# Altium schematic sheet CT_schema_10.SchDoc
size 274 x 160 mm
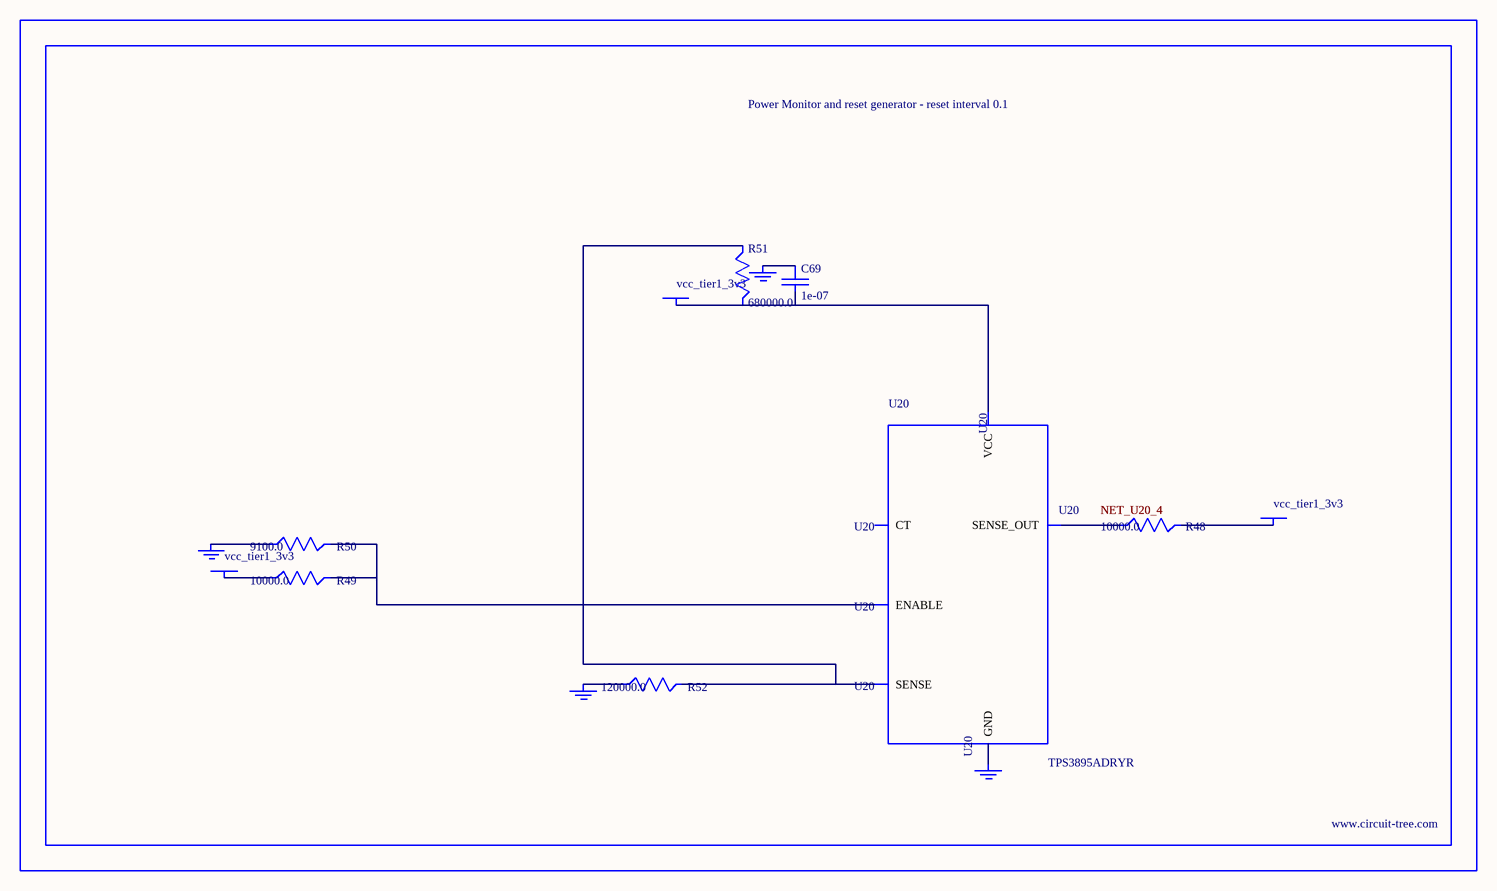
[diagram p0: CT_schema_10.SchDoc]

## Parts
BORDER9  (no value)
C69  1e-07  [C0402]
GND_INSTANCE_9_0  (no value)
GND_INSTANCE_9_1  (no value)
GND_INSTANCE_9_2  (no value)
GND_INSTANCE_9_3  (no value)
POWER_INSTANCE_9_0  vcc_tier1_3v3
POWER_INSTANCE_9_1  vcc_tier1_3v3
POWER_INSTANCE_9_2  vcc_tier1_3v3
R48  10000.0  [R0603]
R49  10000.0  [R0603]
R50  9100.0  [R0603]
R51  680000.0  [R0603]
R52  120000.0  [R0603]
U20  TPS3895ADRYR  [SON-6]

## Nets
NetC69_1: C69.1 GND_INSTANCE_9_2.0(GND)
NetC69_2: C69.2 POWER_INSTANCE_9_2.0(PWR) R51.2 U20.6(VCC)
NetGND_INSTANCE_9_0_0: GND_INSTANCE_9_0.0(GND) R50.1
NetGND_INSTANCE_9_1_0: GND_INSTANCE_9_1.0(GND) R52.1
NetGND_INSTANCE_9_3_0: GND_INSTANCE_9_3.0(GND) U20.2(GND)
NetPOWER_INSTANCE_9_0_0: POWER_INSTANCE_9_0.0(PWR) R49.1
NetPOWER_INSTANCE_9_1_0: POWER_INSTANCE_9_1.0(PWR) R48.2
NetR48_1: R48.1 U20.4(SENSE_OUT)
NetR49_2: R49.2 R50.2 U20.1(ENABLE)
NetR51_1: R51.1 R52.2 U20.3(SENSE)

Not connected (* = marked no-connect by the designer): U20 5(CT)

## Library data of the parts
BORDER9 = BORDER_PAGE9
C69 = C0402C104K3RACTU
GND_INSTANCE_9_0-GND_INSTANCE_9_3 = GND
POWER_INSTANCE_9_0-POWER_INSTANCE_9_2 = PWR
R48 R49 = RC0603JR-0710KL
R50 = RC0603JR-079K1L
R51 = RC0603JR-07680KL
R52 = RC0603JR-07120KL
